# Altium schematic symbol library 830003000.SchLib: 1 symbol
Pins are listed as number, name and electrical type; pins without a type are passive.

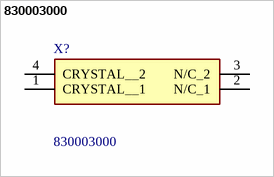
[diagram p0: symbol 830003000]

## 830003000
designator X?
32.768 kHz +/-20ppm Crystal 12.5pF 50 kOhms 4-SOJ, 5.5mm pitch; Manufacturer_Name: Wurth Elektronik; Geometry.Height: 2.5mm
footprint 830003000
pins: 1 CRYSTAL__1, 2 N/C_1, 3 N/C_2, 4 CRYSTAL__2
